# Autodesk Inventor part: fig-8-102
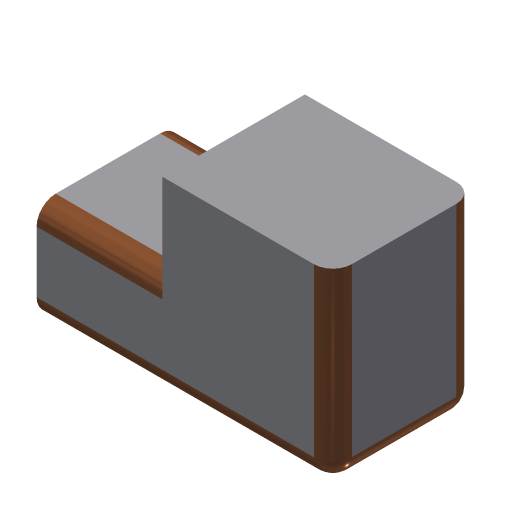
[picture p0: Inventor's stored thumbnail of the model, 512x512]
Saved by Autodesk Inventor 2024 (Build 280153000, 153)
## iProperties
Shininess: 64.0
Length Units: 11269
Angle Units: 11279
Time Units: 11290
Mass Units: 11283
Length Display Precision: 3
Angle Display Precision: 2
Compacted: True
Part Number: fig-8-102
Document SubType Name: Modeling
Created: 2002-12
Designer: deepak
Density: 1 g/cm^3
Material: Generic
Appearance: Default
Density: 0.0
Volumn: 0.0
Area: 0.0
PropertySet Name: Model Information
Control State: 0
Master: False
Checked Out: False
Author: deepak
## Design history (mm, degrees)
sketch "Sketch1"
  geometry: L1 (-26.972, 23.346)-(8.906, 23.346); L2 (8.906, 23.346)-(8.906, 5.025); L3 (8.906, -15.84)-(-26.972, -15.84); L4 (-26.972, -15.84)-(-26.972, 23.346); L5 (8.906, -15.84)-(35.369, -15.84); L6 (35.369, -15.84)-(35.369, 5.025); L7 (35.369, 5.025)-(8.906, 5.025)
  constraints: 14 end point, 3 parallel, 2 horizontal, 2 perpendicular
extrude "Extrusion1" new body sketch "Sketch1" stored distance "d0" = 30; taper "d1" = 0 deg
fillet "Fillet1" dims "d2" = 4, "d3" = 4
delete_face "Delete Face1"
delete_face "Delete Face2"
delete_face "Delete Face3"
body "Solid1"
